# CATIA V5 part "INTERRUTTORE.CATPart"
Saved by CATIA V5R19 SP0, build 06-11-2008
Part number: INTERRUTTORE
Bounding box of the stored display mesh (mm): x 42.6 to 46.6, y 3.174 to 6.85, z 47.192 to 56.786
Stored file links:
  C:\Users\sisca\Desktop\HELTEC_CASE\INTERRUTTORE.CATPart
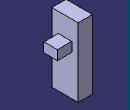
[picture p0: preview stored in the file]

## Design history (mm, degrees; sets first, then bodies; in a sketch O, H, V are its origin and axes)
Set1
  DatumSurface1
Body1 (main body)
  Sketch1 on face of DatumSurface1, origin (44.6, 0, 0), H (0, 1, 0), V (0, 0, 1)
    line L1 (3.1744, 56.7863) -> (6.8498, 56.7863)
    line L2 (6.8498, 56.7863) -> (6.8498, 47.1916)
    line L3 (6.8498, 47.1916) -> (3.1744, 47.1916)
    line L4 (3.1744, 47.1916) -> (3.1744, 56.7863)
    horizontal: L1 H, L3 H
    vertical: L2 V, L4 V
  Pad1: profile Sketch1, direction (-1, 0, 0), length 2
  Sketch2 on start face of Pad1, origin (44.6, 0, 0), H (0, 1, 0), V (0, 0, 1)
    line L1 (4.0659, 54.101) -> (5.9551, 54.101)
    line L2 (5.9551, 54.101) -> (5.9551, 52.7749)
    line L3 (5.9551, 52.7749) -> (4.0659, 52.7749)
    line L4 (4.0659, 52.7749) -> (4.0659, 54.101)
    horizontal: L1 H, L3 H
    vertical: L2 V, L4 V
  Pad2: profile Sketch2, direction (1, 0, 0), length 2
